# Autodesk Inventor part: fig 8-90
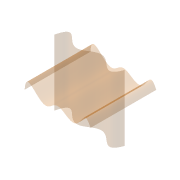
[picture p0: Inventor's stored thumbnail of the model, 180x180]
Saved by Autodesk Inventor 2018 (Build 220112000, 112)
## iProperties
Shininess: 64.0
Length Units: 11269
Angle Units: 11279
Time Units: 11290
Mass Units: 11283
Length Display Precision: 3
Angle Display Precision: 2
Compacted: True
Part Number: fig 8-90
Document SubType Name: Modeling
Created: 2003-08
Designer: Owner
Manufacturer: Standard
Standards Organization: Custom
Density: 1 g/cm^3
Material: Generic
Appearance: Default
Density: 0.0
Volumn: 0.0
Area: 0.0
PropertySet Name: Model Information
Control State: 0
Master: False
Checked Out: False
Author: Owner
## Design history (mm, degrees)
sketch "Sketch1"
  geometry: 7 further points
  constraints: 7 other
  dimensions: "d0" = 80 horizontal distance of point (40, 1.742) point (-40, -4.065); "d1" = 40 horizontal distance of point (0, 0) point (-40, -4.065)
extrude_surface "ExtrusionSrf1" sketch "Sketch1" dims "d2" = 80, "d3" = 0
sketch "Sketch2"
  geometry: L1 (40, 0)-(40, -40) reference; L2 (-40, 0)-(-40, -40) reference; 7 further points
  constraints: 2 point on line, 7 other
extrude_surface "ExtrusionSrf2" sketch "Sketch2" dims "d4" = 80, "d5" = 0
sketch "Sketch3"
  geometry: 2 further points
  constraints: 4 other
sketch "Sketch4"
  geometry: L1 (52.956, 12.425)-(-10.974, 12.425); A1 r 27.841 centre (-10.974, -15.416) between (-10.974, 12.425) and (-7.259, -43.008)
  constraints: 2 end point, 2 point on circle, 1 centre point, 1 horizontal, 1 tangent
body "Srf1"
body "Srf2"
